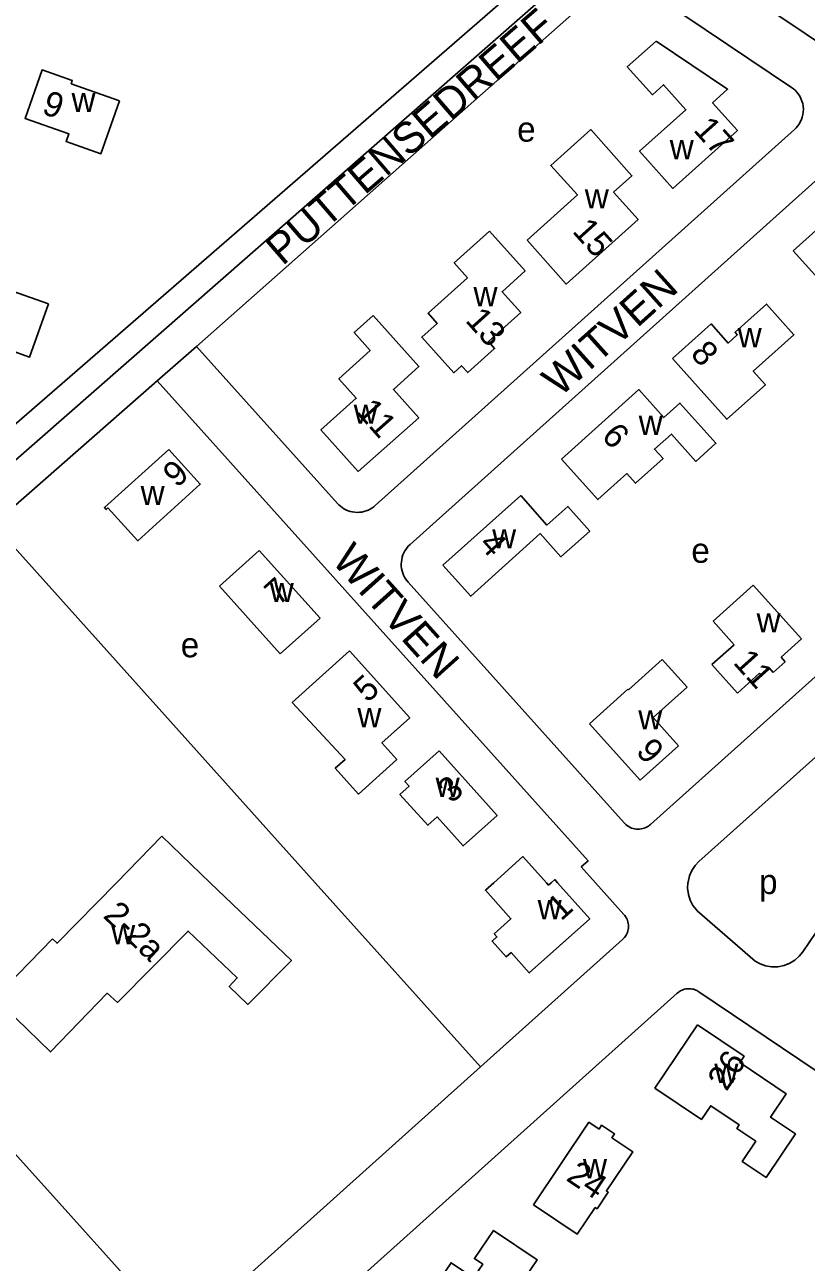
# Model space of a CAD drawing. Extents: x 162804 to 165059, y 381530 to 382901.
# Drawn here: x 163898.9 to 164024.6, y 381689 to 381888 of the extents above; entities that cross this region are included whole.
import ezdxf

# ---------------------------------------------------------------- set-up
doc = ezdxf.new("R2010")
doc.units = 0
for name, color, linetype in [('BLT_Basislijn', 7, 'Continuous'), ('BLT_Bebouwing', 7, 'Continuous'), ('BLT_Centroide', 7, 'Continuous'), ('BLT_Huisnummer', 7, 'Continuous'), ('BLT_Huisnummer_reeks', 7, 'Continuous'), ('BLT_Straatnaam', 7, 'Continuous'), ('BLT_Vlakafsluiter', 7, 'Continuous')]:
    doc.layers.add(name, color=color, linetype=linetype)

msp = doc.modelspace()

# ---------------------------------------------------------------- linework, layer by layer
at = {"layer": 'BLT_Basislijn'}
for p, q in [((164004.28, 381900.2), (164087.97, 381843.76)), ((163960.96, 381866.73), (163994.65, 381896.56)), ((163955.29, 381810.68), (164022.71, 381871.19)), ((163960.96, 381866.73), (163926.53, 381836.29)), ((164031.5, 381867.79), (163960.9, 381804.43)), ((163926.53, 381836.29), (163949.21, 381811.01)), ((163999.57, 381759.39), (164081.86, 381833.24)), ((164071.47, 381810.95), (164007.35, 381753.41)), ((163945.65, 381750), (163893.9, 381807.67)), ((163960.57, 381798.36), (163995.33, 381759.62)), ((163972.23, 381720.39), (163945.65, 381750)), ((164024.05, 381738.87), (164031.55, 381750)), ((164006.93, 381745.64), (164007.08, 381745.48)), ((164007.08, 381745.48), (164016.41, 381737.39)), ((163972.23, 381720.39), (163995.08, 381740.89)), ((164003.84, 381732.23), (163953, 381686.6)), ((163923.85, 381676.97), (163902.6, 381700.58))]:
    msp.add_line(p, q, dxfattribs=at)
for points in [[(163942.85, 382045.24), (163943.88, 382045.91), (163944.68, 382046.18), (163945.43, 382046.3), (163946.28, 382046.34), (163947.14, 382046.2), (163947.91, 382045.97), (163948.94, 382045.37), (163974.77, 382023.71), (164048.11, 381956.56), (164048.67, 381955.87), (164048.35, 381950.3), (163846.25, 381773.14), (163842.47, 381770.18), (163838.71, 381770.12), (163836.54, 381770.96)], [(163942.85, 382045.24), (163967.78, 382024.92), (164044.46, 381954.63), (164045.58, 381953.26), (163979.85, 381895.4), (163836.54, 381770.96)], [(164022.24, 381877.95), (163994.65, 381896.56)], [(164022.71, 381871.19), (164022.97, 381871.44), (164023.21, 381871.73), (164023.44, 381872.05), (164023.65, 381872.39), (164023.82, 381872.77), (164023.96, 381873.17), (164024.06, 381873.59), (164024.12, 381874.02), (164024.14, 381874.46), (164024.11, 381874.91), (164024.03, 381875.34), (164023.91, 381875.76), (164023.75, 381876.16), (164023.56, 381876.54), (164023.33, 381876.89), (164023.08, 381877.2), (164022.81, 381877.49), (164022.53, 381877.74), (164022.24, 381877.95)], [(163893.9, 381807.67), (163920.22, 381830.74)], [(163990.73, 381750), (163988.43, 381752.56), (163989.51, 381753.52), (163920.22, 381830.74)], [(163949.21, 381811.01), (163949.44, 381810.78), (163949.69, 381810.56), (163949.96, 381810.35), (163950.26, 381810.16), (163950.58, 381809.99), (163950.91, 381809.85), (163951.26, 381809.74), (163951.63, 381809.66), (163952, 381809.6), (163952.37, 381809.58), (163952.74, 381809.6), (163953.11, 381809.64), (163953.47, 381809.72), (163953.82, 381809.82), (163954.16, 381809.95), (163954.47, 381810.11), (163954.76, 381810.28), (163955.04, 381810.48), (163955.29, 381810.68)], [(163960.9, 381804.43), (163960.66, 381804.2), (163960.44, 381803.95), (163960.24, 381803.68), (163960.05, 381803.38), (163959.88, 381803.07), (163959.74, 381802.73), (163959.63, 381802.38), (163959.54, 381802.02), (163959.49, 381801.65), (163959.47, 381801.28), (163959.48, 381800.9), (163959.53, 381800.53), (163959.6, 381800.17), (163959.71, 381799.82), (163959.84, 381799.49), (163959.99, 381799.18), (163960.17, 381798.88), (163960.36, 381798.61), (163960.57, 381798.36)], [(163995.33, 381759.62), (163995.49, 381759.46), (163995.67, 381759.3), (163995.86, 381759.16), (163996.06, 381759.03), (163996.28, 381758.91), (163996.52, 381758.81), (163996.76, 381758.73), (163997.02, 381758.67), (163997.27, 381758.64), (163997.54, 381758.62), (163997.8, 381758.63), (163998.05, 381758.66), (163998.31, 381758.72), (163998.55, 381758.79), (163998.78, 381758.88), (163999, 381758.99), (163999.21, 381759.11), (163999.4, 381759.25), (163999.57, 381759.39)], [(164007.35, 381753.41), (164006.74, 381752.76), (164006.22, 381751.98), (164005.82, 381751.09), (164005.59, 381750.12), (164005.58, 381750)], [(163995.29, 381744.91), (163990.73, 381750)], [(164005.58, 381750), (164005.53, 381749.11), (164005.66, 381748.11), (164005.96, 381747.18), (164006.39, 381746.35), (164006.93, 381745.64)], [(163995.08, 381740.89), (163995.23, 381741.04), (163995.38, 381741.2), (163995.51, 381741.39), (163995.64, 381741.58), (163995.75, 381741.79), (163995.84, 381742.01), (163995.92, 381742.25), (163995.97, 381742.49), (163996.01, 381742.73), (163996.02, 381742.98), (163996.01, 381743.23), (163995.98, 381743.47), (163995.93, 381743.71), (163995.86, 381743.94), (163995.78, 381744.16), (163995.67, 381744.37), (163995.56, 381744.57), (163995.43, 381744.75), (163995.29, 381744.91)], [(164016.41, 381737.39), (164017.19, 381736.95), (164018.07, 381736.63), (164019.04, 381736.47), (164020.04, 381736.48), (164021.03, 381736.67), (164021.96, 381737.04), (164022.79, 381737.55), (164023.49, 381738.18), (164024.05, 381738.87)], [(163902.6, 381700.58), (163877.89, 381728.02), (163875.83, 381730.23), (163871.2, 381733.44), (163866.88, 381735.3), (163862.11, 381736.41), (163855.15, 381736.66)], [(164007.34, 381732.47), (164007.18, 381732.57), (164007.01, 381732.66), (164006.84, 381732.74), (164006.65, 381732.81), (164006.46, 381732.87), (164006.26, 381732.91), (164006.06, 381732.94), (164005.86, 381732.96), (164005.65, 381732.96), (164005.45, 381732.95), (164005.24, 381732.92), (164005.04, 381732.87), (164004.85, 381732.82), (164004.66, 381732.74), (164004.48, 381732.66), (164004.3, 381732.57), (164004.14, 381732.46), (164003.99, 381732.35), (164003.84, 381732.23)], [(164027.03, 381720.94), (164026.22, 381719.74), (164007.34, 381732.47)], [(163972.23, 381720.39), (163923.85, 381676.97)]]:
    msp.add_lwpolyline(points, dxfattribs=at)
at = {"layer": 'BLT_Bebouwing'}
for p, q in [((163930.24, 381797.72), (163936.64, 381803.47)), ((163936.64, 381803.47), (163946.42, 381792.56)), ((163940.02, 381786.82), (163930.24, 381797.72)), ((164009.62, 381792.06), (164016.09, 381797.87)), ((164016.09, 381797.87), (164023.84, 381789.24)), ((163946.42, 381792.56), (163940.02, 381786.82)), ((164012.99, 381788.3), (164009.62, 381792.06)), ((164023.84, 381789.24), (164020.57, 381786.3)), ((164009.42, 381785.1), (164012.99, 381788.3)), ((163996, 381781.03), (164001.44, 381785.91)), ((164001.44, 381785.91), (164005.44, 381781.45)), ((164013.56, 381780.48), (164009.42, 381785.1)), ((164018.63, 381784.56), (164017.37, 381783.43)), ((164019.3, 381783.82), (164018.63, 381784.56)), ((164021.24, 381785.56), (164019.3, 381783.82)), ((164020.57, 381786.3), (164021.24, 381785.56)), ((164017.1, 381783.72), (164013.56, 381780.48)), ((164017.37, 381783.43), (164017.1, 381783.72)), ((163989.75, 381775.57), (163995.93, 381781.12)), ((163995.93, 381781.12), (163996, 381781.03)), ((164005.44, 381781.45), (164000, 381776.58)), ((164000, 381776.58), (164004.08, 381772.04)), ((163997.9, 381766.49), (163989.75, 381775.57)), ((164004.08, 381772.04), (163997.9, 381766.49)), ((163920.97, 381757.47), (163913.66, 381750))]:
    msp.add_line(p, q, dxfattribs=at)
for points in [[(164000.45, 381885.41), (163995.83, 381881.27), (163999.87, 381876.77), (164001.65, 381878.37), (164005.25, 381874.36), (163997.8, 381867.67), (164003.15, 381861.7), (164013.54, 381871.03), (164009.54, 381875.49), (164011.95, 381877.65)], [(164022.51, 381851.67), (164034.42, 381862.32), (164040.34, 381855.74), (164028.43, 381845.05)], [(163973.67, 381854.83), (163979.4, 381848.42), (163975.7, 381845.08), (163978.69, 381841.73), (163973.5, 381837.07), (163974.47, 381835.94), (163970.17, 381832.06), (163969.18, 381833.16), (163967.91, 381832.05), (163962.78, 381837.77), (163965.25, 381839.98), (163963.78, 381841.63), (163970.1, 381847.32), (163967.99, 381849.71)], [(164003.11, 381834.36), (164009.3, 381839.89), (164012.04, 381836.82), (164013.51, 381838.15), (164013.15, 381838.56), (164018.23, 381843.09), (164022.63, 381838.17), (164016.07, 381832.3), (164018.03, 381830.11), (164011.83, 381824.57)], [(163954.97, 381841.25), (163962.32, 381833.03), (163958.22, 381829.37), (163962.29, 381824.81), (163952.54, 381816.17), (163946.56, 381822.88), (163952.23, 381827.94), (163949.46, 381831.06), (163954.47, 381835.6), (163951.9, 381838.5)], [(163985.24, 381818.16), (163997.66, 381829.33), (164001.7, 381824.84), (164004.3, 381827.17), (164010.09, 381820.71), (164006.84, 381817.79), (164002.92, 381822.17), (164000.19, 381819.77), (164001.57, 381818.23), (163997.15, 381814.28), (163995.77, 381815.83), (163991.11, 381811.64)], [(163922.1, 381819.72), (163911.73, 381810.35), (163912.02, 381810.03), (163912.3, 381810.29), (163917.1, 381805.03), (163927.15, 381814.13)], [(163966.18, 381801.07), (163978.7, 381812.29), (163982.9, 381807.55), (163986.27, 381810.53), (163989.78, 381806.56), (163985.13, 381802.45), (163981.83, 381806.17), (163970.64, 381796.1)], [(163951.15, 381787.32), (163960.84, 381776.52), (163956.37, 381772.5), (163958.76, 381769.81), (163952.58, 381764.27), (163948.86, 381768.43), (163950.43, 381769.81), (163941.94, 381779.02)], [(163965.57, 381771.21), (163974.89, 381760.84), (163969.42, 381755.93), (163965.25, 381760.58), (163963.76, 381759.24), (163959.26, 381764.21), (163960.74, 381765.55), (163960.07, 381766.29)], [(163980.72, 381698.2), (163989.66, 381711.47), (163991.29, 381710.37), (163991.7, 381710.98), (163993.78, 381709.59), (163993.36, 381708.97), (163996.7, 381706.72), (163992.46, 381700.42), (163992.76, 381700.22), (163990.96, 381697.56), (163990.66, 381697.76), (163987.76, 381693.45)], [(163963.18, 381682.49), (163967.48, 381688.87), (163971.1, 381686.43), (163972.59, 381688.63), (163971.25, 381689.54), (163974.31, 381694.08), (163981.31, 381689.36), (163978.25, 381684.83), (163976.81, 381685.8), (163975.31, 381683.59), (163977.41, 381682.17), (163973.11, 381675.8), (163972.2, 381676.41), (163971.64, 381675.58), (163968.94, 381677.4), (163969.5, 381678.23)]]:
    msp.add_lwpolyline(points, close=True, dxfattribs=at)
for points in [[(163914.17, 381875.79), (163906.39, 381878.54), (163906.57, 381879.04), (163901.72, 381880.75), (163898.98, 381872.97), (163906.03, 381870.48), (163905.58, 381869.22), (163911.15, 381867.25), (163914.17, 381875.79)], [(163979.7, 381853.4), (163987.79, 381860.66), (163983.52, 381865.41), (163989.94, 381871.17), (163996.58, 381863.75), (163993.62, 381861.08), (163997.56, 381856.68), (163986.02, 381846.32), (163979.7, 381853.4)], [(163902.74, 381843.12), (163894.96, 381845.88), (163895.12, 381846.31), (163890.27, 381848.03), (163887.55, 381840.34), (163894.6, 381837.84), (163894.14, 381836.53), (163899.71, 381834.56), (163902.74, 381843.12)], [(163928.76, 381750), (163920.97, 381757.47)], [(163982.84, 381750), (163979.05, 381754.22), (163974.35, 381750)], [(163984.62, 381750), (163984.15, 381750.52), (163983.57, 381750)], [(163903.36, 381741), (163894.09, 381731.47), (163897.54, 381728.17), (163903.09, 381722.79), (163912.2, 381732.24), (163913.86, 381730.76), (163925.19, 381742.22), (163933.11, 381734.68), (163931.8, 381733.31), (163934.81, 381730.43), (163941.8, 381737.51), (163928.76, 381750)], [(163913.66, 381750), (163904.13, 381740.28), (163903.36, 381741)], [(163984.62, 381750), (163989.8, 381744.22), (163980.07, 381735.49), (163977.13, 381738.76), (163976.36, 381738.07), (163974.09, 381740.61), (163974.86, 381741.29), (163974.42, 381741.78), (163977.12, 381744.21), (163973, 381748.79), (163974.35, 381750)], [(163982.84, 381750), (163983.17, 381749.64), (163983.57, 381750)], [(164007.14, 381727.12), (164000.28, 381716.96), (164007.75, 381711.92), (164009.25, 381714.14), (164013.83, 381711.05), (164013.44, 381710.47), (164016.49, 381708.41), (164014.3, 381705.18), (164018.15, 381702.59), (164022.86, 381709.6), (164018.88, 381712.28), (164021.4, 381716.04), (164013.93, 381721.08), (164014.6, 381722.08), (164007.14, 381727.12)]]:
    msp.add_lwpolyline(points, dxfattribs=at)
at = {"layer": 'BLT_Vlakafsluiter'}
msp.add_line((163926.53, 381836.29), (163920.22, 381830.74), dxfattribs=at)

# ---------------------------------------------------------------- texts
at = {"layer": 'BLT_Centroide'}
for s, p in [('w', (163906.44, 381874)), ('e', (163978.11, 381869.22)), ('w', (164002.65, 381866.4)), ('w', (163988.99, 381858.48)), ('w', (163971.09, 381842.75)), ('w', (164013.58, 381836.16)), ('w', (163951.83, 381823.83)), ('w', (163997.66, 381822.05)), ('w', (163917.56, 381810.76)), ('w', (163974.09, 381803.81)), ('e', (164006.12, 381801.47)), ('w', (163938.33, 381795.16)), ('w', (164016.62, 381790.28)), ('e', (163924.01, 381786.27)), ('w', (163952.42, 381775.02)), ('w', (163997.59, 381774.66)), ('w', (163965, 381763.81)), ('p', (164017.01, 381748.18)), ('w', (163981.41, 381744.14)), ('w', (163912.82, 381740.12)), ('w', (164009.82, 381717.81)), ('w', (163988.7, 381702.47))]:
    msp.add_text(s, height=4, dxfattribs=at).set_placement(p)
at = {"layer": 'BLT_Huisnummer'}
for s, rotation, p in [('9', 340.5204, (163901.49, 381873.8)), ('17', 311.9038, (164006.31, 381871.03)), ('15', 311.9054, (163986.84, 381854.73)), ('13', 311.902, (163969.65, 381840.37)), ('8', 311.9097, (164005.83, 381834.98)), ('11', 311.4989, (163952.1, 381825.71)), ('6', 311.9058, (163991.52, 381821.74)), ('9', 41.9033, (163923.39, 381813.41)), ('4', 311.4989, (163971.8, 381804.36)), ('7', 41.9033, (163939.74, 381794.45)), ('11', 311.8971, (164012.71, 381785.35)), ('5', 41.9033, (163954.03, 381778.84)), ('9', 311.8971, (163997.06, 381771.02)), ('3', 41.9033, (163967.57, 381762.63)), ('1', 41.9033, (163985.17, 381743.74)), ('26', 56.0068, (164011.76, 381716.31)), ('24', 326.0403, (163985.81, 381702.23))]:
    msp.add_text(s, height=4, rotation=rotation, dxfattribs=at).set_placement(p)
at = {"layer": 'BLT_Huisnummer_reeks'}
msp.add_text('2-2a', height=4, rotation=316.2211, dxfattribs=at).set_placement((163911.37, 381744.54))
at = {"layer": 'BLT_Straatnaam'}
for s, rotation, p in [('JAN SLUYTERSWEG', 70.5997, (163879.76, 381854.2)), ('PUTTENSEDREEF', 40.7413, (163940.37, 381849.14)), ('WITVEN', 41.9064, (163984.98, 381828)), ('WITVEN', 311.9038, (163948.11, 381801.73))]:
    msp.add_text(s, height=5, rotation=rotation, dxfattribs=at).set_placement(p)

doc.saveas('drawing.dxf')
